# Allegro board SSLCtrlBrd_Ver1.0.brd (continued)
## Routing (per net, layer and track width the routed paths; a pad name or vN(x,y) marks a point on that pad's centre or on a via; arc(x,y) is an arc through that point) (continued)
+5V: length 235.9
  TOP w0.152: v2(19.81,61.75) 19.76,61.7 19.76,61.19 21.38,59.57 v2(21.61,59.57) ; U40.6 134.52,29.82 C109.2 v1(135.79,29.62) ; v2(18.08,97.86) 16.68,96.46 R30.2
  TOP w0.254: R18.1 v2(46.3,51.83) ; v2(118.85,34.98) 111.3,34.98 108.99,32.66 v2(108.99,29.79) ; v2(21.62,30.89) 20.83,31.67 C104.2 ; U39.6 v2(18.64,35.91) ; R25.1 v2(134.34,20.85) ; 11.48,75.34 12.18,76.03 v1(20.22,76.03) ; 11.48,75.34 18.49,75.34 20.18,73.65 v1(20.18,73.39) ; 11.48,75.34 J16.3 ; U5.5 103.2,23.09 103.69,23.57 106.38,23.57 v2(106.81,24) ; Q2.2 v2(134.24,19.23)
  TOP w0.305: v2(59.06,80.9) 58.35,80.19 58.35,75.95 57.29,74.89 57.29,69.84 ; R25.1 135.26,19.27 Q2.2
  GND w0.152: v2(21.41,64.31) 21.41,67.18 21.29,67.31 19.92,67.31 19.81,67.41 ; v2(18.08,97.86) 17.21,97.86 16.72,97.36 16.72,96.39
  GND w0.254: v2(19.81,61.75) 19.81,73.03 v1(20.18,73.39)
  GND w0.305: v2(121.87,85.47) 121.84,85.47 121.19,84.81 118.59,84.81 v2(118.26,85.14)
  POWER w0.254: v2(129.42,49.2) 130.2,49.2 132.41,51.41 ; v2(129.4,51.7) 130.6,51.7 131.55,52.65
  POWER w0.305: v2(129.53,46.75) 130.65,46.75 133.94,50.04 ; LS1.1 89.97,68.74 81.71,60.48 65.59,60.48 v2(64.31,61.75)
  BOTTOM w0.152: D34.2 v1(83.83,84.81) ; v2(56.14,97.87) RP7.3 RP7.2 RP7.1 ; D31.2 v1(20.18,73.39) ; v2(21.41,64.31) 21.28,64.45 D27.2 ; D33.2 v1(86.28,84.83) ; D13.2 v2(18.08,97.86) ; D12.2 v2(18.05,100.5) ; D35.2 v1(81.14,84.81) ; D30.2 v1(20.22,76.03) ; D29.2 v2(21.61,59.57)
  BOTTOM w0.254: D28.2 20.08,62.01 v2(19.81,61.75) ; J20.1 137.97,47.12 C76.2 141.48,46.48 142.22,47.22 142.22,48.15 RP11.3 RP11.2 RP11.1 ; C79.2 138.97,77.01 J14.3 ; v2(53.7,72.26) 55.58,74.14 TP2.1 ; J13.3 121.44,94.41 C70.2 ; v2(118.26,85.14) 119.41,86.28 D19.2 ; D23.2 v2(129.42,49.2) ; v2(139.19,90.68) 139.41,90.89 R36.2 ; D15.2 115.7,85.06 v2(115.34,84.71) ; J15.1 10.82,68.22 C83.2 v2(11.99,68.94) ; v2(59.64,62.27) 59.64,57.09 57.58,55.03 48.13,55.03 46.3,53.2 v2(46.3,51.83) ; J11.3 26.23,92.67 C61.2 ; D5.2 133.7,97.62 v2(134.06,97.26) ; D25.2 132.59,78.16 v2(133,78.56) ; v2(136.63,92) 136.63,92.46 136.72,92.55 R35.2 ; J16.3 11.15,75.01 C88.2 ; v2(112.96,84.73) 113.22,85 D16.2 ; D9.2 v2(56.46,83.29) ; v2(53.85,84.9) 53.99,84.76 D10.2 ; J12.1 114.48,93.42 C65.2 116.36,93.93 116.36,96.9 115.85,97.41 RP9.3 RP9.2 RP9.1 ; D18.2 v2(121.87,85.47) ; D24.2 v2(133.01,75.71) ; J17.1 84.03,93.09 C95.2 ; D14.2 110.74,85.21 v2(110.21,84.68) ; v2(106.81,24) 106.81,27.61 v2(108.99,29.79) ; C56.2 54.11,93.22 J10.1 ; D20.2 v2(129.4,51.7) ; D11.2 v2(51.52,84.72)
  BOTTOM w0.305: RP13.1 v2(5.53,68.16) ; RP13.1 v2(6.58,69.14) ; RP13.1 RP13.2 ; RP13.2 RP13.3 v2(8.21,69.11) ; RP13.2 v2(7.39,69.16) ; RP15.1 RP15.2 ; RP15.2 RP15.3 ; RP15.2 v2(86.34,98.43) ; D21.2 v2(129.53,46.75)
  vias: v2(17.17,20.8) v2(17.17,20.09) v2(17.22,19.41) v2(17.2,18.72) v2(17.88,20.83) v2(17.88,20.12) v2(17.88,19.41) v2(17.91,18.72) v2(18.59,20.8) v2(18.59,20.12) v2(63.63,63.75) v2(63.63,63.09) v2(63.63,62.43) v2(63.63,61.77) v2(63.63,61.11) v2(64.21,63.73) v2(64.26,63.07) v2(64.29,62.41) v2(64.31,61.11) v2(64.87,63.73) v2(64.9,63.07) v2(65.51,63.7) v2(65.53,63.07)
+VDD_A: length 13.1
  TOP w0.152: U1.22 v1(73.76,42.23)
  BOTTOM w0.254: C14.1 C13.1 73.71,41.81 73.71,42.19 v1(73.76,42.23) 73.71,42.28 FB1.2 73.71,43.89 73.18,44.42 69.65,44.42 69.12,44.96 69.12,46.33 69.97,47.19 R10.2
GND: length 337.3
  TOP w0.152: v2(39.37,55.25) R87.1 38.48,55.4 C84.1 ; v2(110.57,39.75) 110.03,39.22 U16.2 ; U3.1 77,52.97 v2(76.53,52.5) 76.35,52.32 76.35,49.89 77.4,48.84 78.95,48.84 79.23,49.13 U3.9 ; 102.77,41.45 v2(102.77,39.47) 102.87,39.37 ; 102.77,41.45 102.95,41.63 C71.1 ; 102.77,41.45 102.77,43.64 v2(102.97,43.84) U28.2 ; R104.1 v1(68.86,71.27) ; U31.2 102.95,39.29 102.87,39.37 ; R59.1 v1(96.26,72.95) ; v2(78.18,63.65) 78.82,64.29 R100.1 ; C96.1 v2(83.16,73.22) ; R65.1 v1(96.26,71.47) ; C99.1 18.06,11.51 v2(15.88,13.69) ; U17.2 v2(110.54,44.27) ; v2(84.25,54.28) 84.03,54.05 82.5,54.05 81.42,52.97 U3.18 ; C80.1 103.35,37.31 102.87,37.8 102.87,39.37 ; C80.1 103.35,34.98 R6.1 v2(104.55,34.85) ; C80.1 103.89,36.88 v2(104.35,36.42) ; C91.1 80.21,64.7 R100.1 ; R100.1 76.45,64.7 v2(76.37,64.62) C38.2 ; v2(25.66,32.39) C101.2 R116.2 v2(24.64,30.35) ; U18.3 99.02,54.03 v1(99.02,54.03) ; v2(130.23,31.09) U40.7 134.52,31.09 C109.1 v1(135.79,31.29) ; U19.3 v1(102.85,56.34) ; v2(84.33,59.36) Q1.2 83.26,58.19 R9.1 ; v2(97.91,38.6) 97.41,38.1 D3.2 ; C106.2 v2(122.46,33.96) ; R98.1 v1(68.86,72.75) ; C51.2 v2(129.29,90.47)
  TOP w0.203: C22.2 v1(88.52,27.1) C31.2 ; U1.99 85.07,41.28 84.43,40.64 v1(83.85,40.64) ; v1(69.19,41.53) 69.44,41.28 U1.27 ; v1(80.16,40.31) 80.16,42.14 79.76,42.55 U1.10 ; v1(135.49,84.86) 135.61,84.99 C53.2 ; U1.74 83.76,27.17 84.03,26.9 v1(84.89,26.9)
  TOP w0.254: C89.1 45.98,41.86 v2(45.98,40.34) U34.2 ; v2(117.53,69.67) 116.93,69.08 R78.1 R72.1 ; C43.2 v2(126.71,17.13) ; 56.93,32.13 56.46,31.67 U2.3 53.48,31.67 v2(53.19,31.95) ; 56.93,32.13 56.93,33.43 ; 56.93,32.13 56.93,31.3 56.03,30.4 U2.4 ; R45.1 62.38,49.2 ; 62.38,49.2 63.1,49.2 R13.2 63.12,50.47 62.77,50.83 ; 62.38,49.2 v2(62.38,48.39) ; v2(40.47,62.94) C57.1 40.3,63.96 R48.1 ; C45.2 v2(98.68,62.41) ; v2(97.06,22.38) C32.2 97.23,23.34 98.38,23.34 98.83,22.89 C33.2 ; C87.1 v2(30.37,59.58) ; R74.1 v2(111.05,64.64) ; v2(105.41,63.93) 106.35,64.87 R61.1 106.56,65.05 C66.1 ; 56.89,34.55 56.54,34.2 54.94,34.2 U2.1 ; 56.89,34.55 56.93,34.51 56.93,33.43 ; 56.89,34.55 C3.2 ; C69.1 v2(108.82,73.35) ; R19.2 47.65,49.09 v2(48.16,49.09) ; C78.1 118.98,54.05 v2(119.33,53.7) ; U2.1 v2(54.93,35.1) ; U2.1 54.75,34.39 C16.2 C12.2 50.45,34.42 U4.15 ; 56.93,33.43 57.42,32.94 U2.7 v2(62.47,32.94) ; 56.93,33.43 56.44,32.94 U2.2 v2(53.26,32.94) ; C23.2 65.51,28.35 C26.2 65.48,26.64 C25.2 v2(63.48,26.49) ; v2(95.46,55.07) C46.2 95.44,54.5 D4.1 93.37,54.28 v2(94.03,53.62) ; U38.16 40.78,24.82 v2(41.18,25.22) ; U39.7 v2(19.16,34.64) ; v2(33.73,52.83) 34.46,53.56 U32.7 ; v2(31.46,44.67) R91.1 31.42,45.64 R85.1 ; R53.1 R46.1 29.75,72.57 v2(30.63,73.46) ; C47.2 v2(101.93,60.93) ; C86.1 33.63,59.16 v2(33.07,59.72) ; v2(116,60.83) 115.22,60.05 U29.7 ; J3.8 v2(113.01,25.07) ; v2(74.9,44.68) 74.76,44.54 U1.20 ; C5.2 v2(89.51,43.33) ; U5.2 v2(101.22,21.79) ; J5.1 90.22,50.19 v2(89.49,50.93) ; C104.1 v2(17.3,31.67) ; U25.2 v2(45.77,44.73) ; D7.1 v2(139.05,84.97) ; U20.2 58.75,44.12 R41.1 C49.2 v2(59.64,47.68) ; C62.1 v2(44.3,46.94) ; C20.2 v2(125.96,21.18) ; U21.3 v2(130.28,95.5) ; C19.2 v2(38.69,30.99) ; R31.1 v2(104.57,54.33) ; C60.1 v2(42.95,72.48) ; C48.2 51.54,45.29 v2(50.78,46.05) ; U38.32 v2(24.06,8.32) ; C15.2 v2(46.05,35.66) ; 92.46,21.84 v2(93.12,21.84) ; C6.2 85.04,53.49 v2(84.25,54.28) 83.39,55.14 C8.2
  TOP w0.305: v2(104.03,70) 104.52,69.52 U26.7 ; v2(36.58,69.27) 36.64,69.27 37.27,68.64 U23.7 ; C73.1 v2(115.5,53.01) ; C72.1 v2(112.02,53.77) ; C20.2 127.61,22.93 C21.2 ; U14.3 129.61,15.86 128.93,15.18 C43.2 ; v2(76.46,69.95) 76.48,69.95 77.12,69.32 U35.7
  TOP w0.5: D8.1 v2(58.82,101.54) ; D8.1 v2(61.28,99.83) ; D8.1 v2(58.82,98.31) ; D6.2 v2(133.63,100.3) ; D32.1 v2(88.41,102.02) ; D32.1 v2(90.92,100.06) ; D32.1 v2(88.41,98.64)
  BOTTOM w0.152: v2(63.25,56.54) 62.66,55.96 TP4.1 ; D21.1 128.08,45.45 v2(127.74,45.11) ; D13.1 v2(18.25,96.56) ; D10.1 55.29,84.44 v2(55.42,84.58) ; D11.1 52.82,84.47 v2(52.88,84.53) ; U13.10 v2(77.42,17.02) ; v2(6.35,74.22) 7.14,75.01 C88.1 ; D35.1 v1(82.44,84.81) ; v2(11.97,91.59) 12.64,92.26 Q3.2 ; 56.97,96.47 56.72,96.47 55.98,95.73 55.98,95.48 ; D31.1 20.11,74.69 v2(20.42,75.01) ; v2(10.31,71.73) 10.82,71.22 C83.1 ; D30.1 20.03,77.33 v2(20.42,77.72) ; v2(13.16,90.47) 13.9,91.22 R33.1 ; C10.2 74.83,47.19 C2.1 ; C10.2 C9.2 ; C10.2 v2(73.28,46.56) ; v2(75.16,20.27) U13.15 U13.14 ; v2(84.46,95.3) 84.99,94.77 C95.1 ; C61.1 29.24,92.08 29.9,92.74 29.9,93.99 J11.1 ; D23.1 v2(128.09,47.9) ; 64.94,6.4 v1(68.05,6.4) 68.05,6.4 RP4.5 RP4.6 RP4.7 RP4.8 ; v1(82.93,47.7) 82.93,47.7 C1.1 ; D28.1 v2(21.16,63.31) ; v2(127,50.93) 127.53,50.4 D20.1 ; C79.1 142.75,77.01 v2(143.72,77.98) ; D34.1 v1(85.13,84.81) ; v2(68.28,33.4) 68.66,33.78 C52.2 ; U11.8 v2(65.8,16.44) ; 51.63,6.4 v1(54.76,6.4) 54.76,6.4 RP2.5 RP2.6 RP2.7 RP2.8 ; D29.1 21.28,60.87 v2(21.62,61.21) ; D33.1 v1(87.58,84.81) ; v2(84.15,17.91) C44.2 84.1,18.97 U13.4 ; 78.04,6.3 v1(81.31,6.3) 81.31,6.3 RP6.5 RP6.6 RP6.7 RP6.8 ; U13.3 U13.4 ; U13.4 U13.5 U13.6 80.76,17.67 80.62,17.53 80.62,16.71 80.88,16.46 81.99,16.46 U13.8 v2(83.56,16.37) ; D27.1 v2(20.74,66.38) ; U11.15 58.19,20.35 C42.2 56.16,18.31 v2(55.81,18.31) ; D12.1 v2(18.15,99.2) ; D9.1 v2(57.76,84.58)
  BOTTOM w0.203: v1(69.19,41.53) 69.22,41.56 C30.2 ; C27.2 83.85,39.9 v1(83.85,40.64)
  BOTTOM w0.254: C29.2 75.46,40.13 v2(75.03,40.56) ; C29.2 C13.2 ; C29.2 77.08,39.89 C18.2 ; C65.1 115.17,94.97 v2(115.67,95.48) ; D19.1 120.71,86.31 v2(120.86,86.16) ; C13.2 v2(73.96,40.54) ; C13.2 C14.2 v2(72.46,40.59) ; v2(123.65,86.44) 123.17,86.92 D18.1 ; v2(122.48,99.49) 121.44,98.45 C70.1 ; v2(32.14,22.04) R122.1 34.02,20.96 Q19.2 ; D16.1 v2(114.52,84.44) ; D5.1 132.89,96.73 v2(132.54,97.08) ; C76.1 136.45,46.48 v2(135.82,45.85) ; v2(141.4,92.86) 140.93,93.33 C50.2 ; D25.1 v2(133,76.86) ; v2(76.53,52.5) C4.2 79.25,52.5 C7.2 80.65,52.48 R3.1 ; D15.1 v2(117,84.46) ; D24.1 v2(132.99,74.41) ; C27.2 83.49,39.88 v1(82.93,39.32) C24.2 81.64,39.67 C28.2 v1(80.16,40.31) ; D14.1 v2(112.04,84.36)
  BOTTOM w0.5: v2(88.41,102.02) 88.41,100.1 ; 88.41,100.1 90.88,100.1 v2(90.92,100.06) ; 88.41,100.1 v2(88.41,98.64) ; v2(58.82,98.31) 55.98,95.48 C56.1
  vias: v2(13.85,15.09) v2(13.87,14.4) v2(13.82,13.67) v2(14.53,15.09) v2(14.53,14.4) v2(14.53,13.69) v2(15.17,15.04) v2(15.17,14.35) v2(15.17,13.64) v2(15.88,14.38) v2(15.93,15.06) v2(22.96,66.27) v2(22.99,65.58) v2(23.52,86.64) v2(23.55,85.93) v2(23.62,66.24) v2(23.65,65.56) v2(24.23,86.64) v2(24.26,85.9) v2(24.28,66.22) v2(24.28,65.56) v2(24.95,66.19) v2(24.92,65.56) v2(25.07,72.21) v2(25.05,71.53) v2(25.05,70.84) v2(25.05,70.18) v2(25.58,65.61) v2(25.61,66.27) v2(25.78,72.16) v2(25.76,71.5) v2(25.76,70.82) v2(25.71,70.16) v2(26.47,72.11) v2(26.42,71.45) v2(32.06,52.86) v2(32.06,52.04) v2(32.06,51.21) v2(32.88,52.06) v2(32.9,52.86) v2(32.9,51.21) v2(33.71,52.02) v2(33.71,51.16) v2(34.88,70.99) v2(34.88,70.21) v2(34.88,69.39) v2(35.74,70.97) v2(35.77,70.14) v2(35.77,69.32) v2(36.55,70.97) v2(36.58,70.1) v2(43.54,69.65) v2(43.61,68.83) v2(50.32,53.3) v2(50.32,52.29) v2(50.32,51.27) v2(51.33,53.3) v2(51.33,52.29) v2(51.33,51.27) v2(52.96,81.41) v2(52.96,80.7) v2(52.96,79.32) v2(53.01,80.01) v2(53.9,79.12) v2(53.95,78.46) v2(53.95,77.75) v2(54.59,79.12) v2(54.61,78.44) v2(54.61,77.75) v2(56.92,58.42) v2(56.92,57.71) v2(56.9,57.05) v2(57.58,57.02) v2(57.61,58.42) v2(57.61,57.71) v2(58.27,58.34) v2(58.22,57.66) v2(61.06,58.22) v2(61.09,57.15) v2(61.04,56.52) v2(61.11,59.13) v2(61.62,65.79) v2(62.16,59.13) v2(62.36,65.79) v2(63.05,59.16) v2(63.07,58.22) v2(63.17,57.3) v2(67.57,56.69) v2(67.67,58.67) v2(67.62,58.06) v2(67.59,57.43) v2(68.23,58.06) v2(68.23,57.4) v2(68.2,56.69) v2(68.33,58.67) v2(74.78,69.98) v2(74.81,71.65) v2(74.81,70.82) v2(75.62,71.65) v2(75.62,70.82) v2(75.62,69.98) v2(76.43,71.63) v2(76.46,70.79) v2(80.72,82.96) v2(80.75,82.27) v2(80.77,81.58) v2(80.77,80.92) v2(83.54,70.28) v2(83.52,69.55) v2(102.16,71.88) v2(102.16,71.04) v2(102.16,70.16) v2(103,71.86) v2(103.02,71.02) v2(103.08,70.13) v2(103.86,71.86) v2(103.84,70.94) v2(110.9,70.36) v2(110.9,69.72) v2(114.66,82.35) v2(114.63,81.64) v2(114.66,80.95) v2(114.66,80.26) v2(115.29,82.32) v2(115.29,81.66) v2(115.32,80.95) v2(115.98,81.64) v2(116,82.35) v2(116,80.95) v2(116,62.48) v2(116.03,61.67) v2(116.64,82.32) v2(116.64,81.66) v2(116.66,80.95) v2(116.77,61.67) v2(116.79,62.46) v2(116.82,60.81) v2(117.53,62.46) v2(117.53,61.65) v2(123.67,45.87) v2(123.65,45.19) v2(124.28,45.19) v2(124.26,44.48) v2(124.23,43.79) v2(124.31,45.85) v2(124.87,43.79) v2(124.94,45.85) v2(124.89,45.21) v2(124.89,44.53) v2(125.58,45.19) v2(125.53,44.42) v2(125.53,43.79) v2(125.61,45.87)
GND_OPT: length 91.8
  TOP w0.152: U17.3 114.15,44.27 113.82,43.94 113.82,39.83 114.45,39.19 115.85,39.19 U16.3 116.56,39.22 v1(117.27,39.93) 117.27,41.73 118.39,42.85 v1(118.39,51.08)
  TOP w0.203: v1(119.53,37.62) 122.33,34.82 134.57,34.82 137.34,37.59 139.01,37.59 U22.2
  BOTTOM w0.152: v1(118.39,51.08) 118.39,56.13 117.83,56.69 117.83,59.97 117.83,60.03 119.92,62.11 119.92,75.23 121.72,77.04 126.34,77.04 128.42,79.12 128.42,82.85 129.36,83.79 132.1,83.79 J9.4 ; v1(119.53,37.62) 117.27,39.88 v1(117.27,39.93)
VBAT: length 58.4
  TOP w0.152: C37.1 56.23,50.87
  TOP w0.508: U19.6 105.77,56.34 104.93,57.18 C47.1 104.93,61.49 102.39,64.03 98.88,64.03 91.95,70.97 91.95,76.2 v2(91.26,76.89) ; R43.1 56.8,51.27 C37.1
  GND w1.016: v2(55.42,52.81) 55.42,69.52 61.04,75.13 v2(61.04,76.23)
  vias: v2(14.38,72.54) v2(14.35,71.88) v2(14.94,71.88) v2(15.01,72.54) v2(15.57,71.83) v2(15.62,72.52) v2(20.88,84) v2(20.86,83.31) v2(20.86,82.6) v2(20.86,81.74) v2(20.86,81) v2(20.91,80.42) v2(21.54,84.02) v2(21.54,83.34) v2(21.49,82.6) v2(21.54,81.79) v2(21.59,81.13) v2(21.59,80.44) v2(22.28,81.15) v2(22.3,80.44) v2(22.99,81.15) v2(22.99,80.44) v2(55.32,53.44) v2(55.42,52.2) v2(55.88,52.83) v2(56.36,52.81) v2(56.87,52.81) v2(57.38,52.76) v2(60,76.15) v2(60.51,76.17) v2(61.09,78.64) v2(61.09,77.34) v2(61.04,76.81) v2(61.11,77.95) v2(61.57,77.34) v2(61.6,76.78) v2(61.6,76.2) v2(90.07,78.36) v2(90.07,77.77) v2(90.1,77.17) v2(90.71,78.36) v2(90.71,77.77) v2(90.71,77.17) v2(91.26,77.44) v2(91.29,78.05) v2(124.28,92.08) v2(124.26,91.41) v2(124.28,90.81) v2(124.28,90.14) v2(124.94,92.05) v2(124.94,91.39) v2(124.92,90.78) v2(124.92,90.14) v2(136.12,40.94) v2(136.76,40.92) v2(137.42,40.92) v2(138.03,40.94) v2(138.2,41.63) v2(138.86,41.61) v2(139.55,41.55)
A_OUT_1: length 11.9
  TOP w0.152: 32.82,86.84 32.88,86.91
  TOP w0.254: v2(33.81,80.19) 33.81,77.34 32.54,76.07 32.54,72.08 32.98,71.64 U23.22
  BOTTOM w1.016: J10.8 36.44,95.57 TP19.1
  vias: v2(31.47,86.92) v2(31.47,86.18) v2(31.45,85.47) v2(32.18,86.92) v2(32.18,86.18) v2(32.16,85.5) v2(32.87,86.92) v2(32.87,86.21) v2(32.87,85.5) v2(33.84,80.8) v2(34.5,80.82) v2(34.5,80.16)
A_OUT_2: length 15.7
  TOP w0.254: v2(93.65,80.09) 93.19,79.63 93.19,75.95 93.98,75.16 97.94,75.16 98.99,74.12 99.44,74.12 99.94,73.62 99.94,72.73 100.15,72.52 U26.22
  BOTTOM w1.016: 95.7,93.42 95.7,95.41 TP27.1
  vias: v2(90.32,86.82) v2(90.91,86.84) v2(90.96,86.26) v2(90.96,85.57) v2(91.57,86.82) v2(91.54,86.18) v2(91.54,85.6) v2(92.18,86.18) v2(92.15,85.55) v2(92.2,86.79) v2(93.02,80.75) v2(93.02,80.09) v2(93.65,80.75)
A_OUT_3: length 12.7
  TOP w0.254: v2(124.64,68.99) 124.31,69.32 120.73,69.32 119.51,68.1 119.51,66.17 118.25,64.91 U29.22
  BOTTOM w1.016: J20.8 TP35.1
  vias: v2(124.67,69.62) v2(125.35,69.6) v2(125.33,68.99) v2(129.8,72.06) v2(129.82,71.35) v2(129.85,70.64) v2(130.51,72.06) v2(130.53,71.35) v2(130.56,70.66) v2(131.22,72.06) v2(131.22,71.35) v2(131.24,70.66)
A_OUT_4: length 13.2
  TOP w0.254: v2(24.34,44.32) 27.74,44.32 28.63,45.21 28.63,48.13 29.34,48.84 30.58,48.84 U32.22
  BOTTOM w1.016: J15.8 9.97,49.44 TP43.1
  vias: v2(17.63,43.46) v2(17.6,42.77) v2(17.6,42.09) v2(18.34,43.46) v2(18.32,42.75) v2(18.32,42.04) v2(19.05,43.43) v2(19.03,42.75) v2(19,42.06) v2(23.68,44.98) v2(23.7,44.35) v2(24.34,44.98)
A_OUT_5: length 18.5
  TOP w0.254: v2(63.22,80.16) 63.43,79.96 63.43,76.35 64.16,75.62 66.58,75.62 68.18,74.02 71.96,74.02 72.57,73.41 72.57,72.61 72.86,72.32 U35.22
  BOTTOM w1.016: J17.8 66.09,96.16 TP51.1
  vias: v2(60.89,86.26) v2(60.89,85.57) v2(60.91,86.94) v2(61.57,86.26) v2(61.6,86.94) v2(61.6,85.57) v2(62.28,86.94) v2(62.28,86.26) v2(62.28,85.57) v2(63.25,80.8) v2(63.88,80.77) v2(63.88,80.14)
ADC_BAT_V: length 23.9
  TOP w0.152: v1(72.06,35.71) 72.06,36.12 71.4,36.78 U1.36
  TOP w0.254: R43.2 R45.2 60.17,49.2 60.71,48.67 60.71,46.94 62.36,45.29 62.36,43.99 69.57,36.78 U1.36
  BOTTOM w0.152: C52.1 69.75,35.71 v1(72.06,35.71)
ADC_CAP_V: length 130.1
  TOP w0.152: v1(137.92,85.78) 137.34,85.78 C53.1 ; v1(72.95,35.84) 72.9,35.89 72.9,36.53 72.14,37.28 U1.35 69.86,37.28 66.32,40.82 66.32,42.85 64.97,44.2 v1(64.6,44.2) ; v1(99.95,46.23) 99.9,46.28 97.44,46.28 v1(97.03,45.87) ; R37.1 60.28,42.52 v1(60.63,42.52)
  TOP w0.203: D7.3 139.59,87.45 R44.2 C53.1
  BOTTOM w0.152: v1(137.92,85.78) 135.51,85.78 134.83,86.46 127.43,86.46 126.82,85.85 126.82,79.6 125.58,78.36 120.17,78.36 118.26,76.45 118.26,66.68 115.85,64.26 113.49,64.26 110.77,61.54 110.77,51.26 107.62,48.11 101.58,48.11 99.95,46.48 v1(99.95,46.23) ; v1(97.03,45.87) 96.85,45.69 96.85,44.32 92.08,39.55 89.87,39.55 88.14,37.82 88.14,35.2 86.95,34.01 81.38,34.01 81,33.63 76.36,33.63 74.15,35.84 v1(72.95,35.84) ; v1(60.63,42.52) 62.54,42.52 64.22,44.2 v1(64.6,44.2)
B_OUT_1: length 14.4
  TOP w0.254: v1(34.39,74.52) 34.77,74.15 U23.20
  BOTTOM w0.254: v1(34.39,74.52) 34.75,74.52 36.04,75.82 38.91,75.82 40.06,76.96 v2(40.06,80.29)
  BOTTOM w1.016: TP18.1 38.94,95.53 J10.7
  vias: v2(37.65,87.05) v2(37.65,86.33) v2(37.62,85.62) v2(38.33,87.02) v2(38.33,86.31) v2(38.33,85.62) v2(39.04,87.02) v2(39.04,86.33) v2(39.04,85.62) v2(40.06,80.95) v2(40.69,80.92) v2(40.72,80.34)
B_OUT_2: length 10.7
  TOP w0.152: 99.54,81.97 Q8.3
  TOP w0.254: v2(99.19,80.09) 99.27,80.01 99.27,76.05 100.03,75.29 101.48,75.29 102.02,74.74 U26.20
  BOTTOM w1.016: TP26.1 98.2,95.29 98.2,93.42
  vias: v2(96.73,86.64) v2(96.73,85.95) v2(96.7,85.24) v2(97.46,86.61) v2(97.44,85.93) v2(97.44,85.22) v2(98.17,86.66) v2(98.17,85.95) v2(98.17,85.24) v2(99.24,80.95) v2(99.88,80.95) v2(99.85,80.11)
B_OUT_3: length 8.1
  TOP w0.254: v2(124.59,63.42) 124.46,63.3 120.47,63.3 119.73,62.55 U29.20
  BOTTOM w1.016: J20.7 140.26,64.44 TP34.1
  vias: v2(124.61,62.76) v2(125.28,63.42) v2(125.3,62.74) v2(129.9,65.89) v2(129.92,65.2) v2(129.9,64.47) v2(130.61,65.89) v2(130.61,65.18) v2(130.61,64.47) v2(131.32,65.89) v2(131.32,65.18) v2(131.32,64.47)
B_OUT_4: length 8.4
  TOP w0.254: v2(24.34,51.18) 24.46,51.06 U32.20
  BOTTOM w1.016: TP42.1 9.91,51.94 J15.7
  vias: v2(17.63,49.63) v2(17.63,48.95) v2(17.63,48.23) v2(18.32,49.63) v2(18.32,48.92) v2(18.32,48.23) v2(19,49.63) v2(19,48.9) v2(19,48.18) v2(23.65,51.18) v2(23.62,50.55) v2(24.31,50.55)
B_OUT_5: length 13.5
  TOP w0.254: v2(70.08,80.19) 69.85,79.96 69.85,75.87 70.56,75.16 73.56,75.16 v2(74.02,74.7) 74.04,74.7 74.62,74.13 U35.20
  BOTTOM w1.016: J17.7 68.59,96.15 TP50.1
  vias: v2(67.08,86.87) v2(67.06,86.18) v2(67.03,85.52) v2(67.77,86.87) v2(67.74,86.21) v2(67.72,85.52) v2(68.46,86.89) v2(68.46,86.21) v2(68.46,85.52) v2(69.42,80.87) v2(69.39,80.21) v2(70.06,80.85)
BLE_RX: length 41.7
  TOP w0.152: U1.56 74.76,24.26 72.11,21.62 55.07,21.62 54.43,20.98 46.81,20.98 44.06,18.22 U38.10
BLE_TX: length 40.5
  TOP w0.152: U1.55 74.26,24.57 71.73,22.05 54.38,22.05 53.85,21.51 46.53,21.51 44.34,19.32 U38.11
BOOT0: length 49.6
  TOP w0.152: v1(92.36,24.08) 92.33,24.05 v1(86.41,24.05) ; U1.94 91.37,38.78 92.13,38.02 92.13,33.63 94.82,30.94 v1(94.82,29.82) ; v1(77.6,15.34) v1(85.45,15.34)
  BOTTOM w0.152: v1(85.45,15.34) 85.45,23.09 v1(86.41,24.05) ; RP5.1 78.02,13.65 77.6,14.07 v1(77.6,15.34) ; v1(94.82,29.82) 94.82,26.39 92.51,24.08 v1(92.36,24.08)
BOOT1: length 17.6
  TOP w0.152: v1(64.75,42.57) 64.7,42.62 64.7,42.67 63.6,43.76 63.6,47.52 64.8,48.72 R13.1 ; v1(64.37,40.92) 64.37,40.89 68.98,36.28 U1.37
  BOTTOM w0.152: v1(64.37,40.92) 64.37,41 64.75,41.38 64.75,42.57 v1(64.75,42.57)
BUZZER: length 17.1
  TOP w0.152: U1.16 76.76,44.51 74.53,46.74 74.53,54.2 R8.1
C_OUT_1: length 17
  TOP w0.254: v1(36.58,74.96) 35.77,74.14 U23.18
  BOTTOM w0.254: v2(46.33,80.24) 45.54,80.24 40.26,74.96 v1(36.58,74.96)
  BOTTOM w1.016: J10.6 41.44,95.49 TP17.1
  vias: v2(44.02,86.94) v2(44.02,86.26) v2(44.02,85.55) v2(44.71,86.94) v2(44.73,86.26) v2(44.73,85.55) v2(45.42,86.94) v2(45.42,86.26) v2(45.42,85.55) v2(46.31,80.92) v2(46.99,80.95) v2(46.99,80.31)
C_OUT_2: length 9.7
  TOP w0.254: v2(105.44,80.11) 105.36,80.04 105.36,78.21 103.02,75.86 U26.18
  BOTTOM w1.016: TP25.1 100.7,95.39 100.7,93.42
  vias: v2(102.87,86.77) v2(102.87,86.06) v2(102.87,85.37) v2(103.56,86.77) v2(103.56,86.08) v2(103.58,85.37) v2(104.27,86.77) v2(104.27,86.06) v2(104.27,85.34) v2(105.41,80.75) v2(106.07,80.8) v2(106.1,80.09)
C_OUT_3: length 11.4
  TOP w0.254: U29.18 119.12,61.54 120.02,61.54 120.3,61.27 120.77,61.27 120.8,61.24 122.4,61.24 123.47,60.17 123.47,57.63 124.59,56.52 v2(124.61,56.52)
  BOTTOM w1.016: J20.6 140.26,61.94 TP33.1
  vias: v2(124.61,57.18) v2(125.25,57.18) v2(125.28,56.52) v2(130.18,59.51) v2(130.13,58.8) v2(130.13,58.14) v2(130.69,58.17) v2(130.76,59.49) v2(130.74,58.83) v2(131.37,58.78) v2(131.32,58.12) v2(131.4,59.49)
C_OUT_4: length 11.3
  TOP w0.254: U32.18 29.15,52.06 26.52,54.69 26.52,56.29 26.11,56.69 24.34,56.69 24.28,56.74
  BOTTOM w1.016: J15.6 9.97,54.44 TP41.1
  vias: v2(17.68,55.85) v2(17.66,55.17) v2(17.63,54.46) v2(18.42,55.85) v2(18.42,55.17) v2(18.39,54.48) v2(19.1,55.85) v2(19.1,55.14) v2(19.13,54.46) v2(23.68,57.4) v2(23.68,56.74) v2(24.34,57.4) v2(24.34,56.72)
C_OUT_5: length 9.9
  TOP w0.254: U35.18 75.62,79.53 v2(76.25,80.16)
  BOTTOM w1.016: J17.6 71.09,96.09 TP49.1
  vias: v2(73.23,86.89) v2(73.2,86.18) v2(73.2,85.47) v2(73.89,86.89) v2(73.89,86.18) v2(73.92,85.47) v2(74.58,86.87) v2(74.58,86.18) v2(74.6,85.47) v2(75.59,80.92) v2(75.62,80.19) v2(76.23,80.92)
CAP_V_IN: length 4.8
  TOP w0.254: R44.1 133.32,87.45 J9.2
  BOTTOM w0.254: J9.2 133.27,89.82 TP12.1
CHIP: length 60.1
  TOP w0.152: R31.2 102.87,52.93 102.87,54.69 102.49,55.07 U19.4 ; R31.2 102.9,51.94 105.51,49.33 105.51,46.99 v1(105.34,46.81) ; R31.2 102.57,52.58 v1(102.06,52.58) ; U1.26 69.96,41.78 69.04,42.7 69.04,43.94 67.85,45.14 v1(67.85,45.8) ; R27.2 107.39,45.14 v1(107.39,44.02)
  BOTTOM w0.152: v1(67.85,45.8) 67.85,47.6 68.94,48.69 91.09,48.69 94.97,52.58 v1(102.06,52.58) ; v1(107.39,44.02) 105.34,46.08 v1(105.34,46.81)
CHIP_OUT: length 61
  TOP w0.152: U19.5 107.14,55.07 v1(107.83,54.38) ; U17.4 114.33,46.81 114.1,47.04 114.1,49.1 110.39,52.81 v1(107.06,52.81)
  BOTTOM w0.152: TP11.1 128.55,87.55 126.39,87.55 113.87,75.03 113.87,70.1 107.55,63.78 107.55,54.66 v1(107.83,54.38) 107.83,53.57 v1(107.06,52.81)
  BOTTOM w0.254: TP11.1 130.71,87.53 J9.1
DIP_SW_CLK: length 26.4
  TOP w0.152: v1(78.46,22.33) 79.26,23.12 U1.65
  BOTTOM w0.152: U11.2 68.79,20.35 70.06,19.08 72.62,19.08 75.92,22.38 78.41,22.38 v1(78.46,22.33) 78.46,22.3 80.5,20.27 U13.2
DIP_SW_D: length 35
  TOP w0.152: v1(55.86,17.02) 56.54,17.7 74.75,17.7 79.76,22.71 U1.66
  BOTTOM w0.152: U11.9 58.85,16.46 56.29,16.46 55.86,16.89 v1(55.86,17.02)
DIP_SW_LD: length 25.7
  TOP w0.152: v1(78.28,23.24) 78.76,23.71 U1.64
  BOTTOM w0.152: U11.1 68.97,21 70.44,19.53 72.24,19.53 75.9,23.19 78.23,23.19 v1(78.28,23.24) 78.49,23.24 80.81,20.92 U13.1
ENCODER_A_1: length 29.5
  TOP w0.152: U1.23 73.26,44.91 70.79,47.37 64.52,47.37 64.49,47.4 v1(64.37,47.4) ; U25.6 48.95,45.67 v1(48.97,45.64)
  BOTTOM w0.152: v1(64.37,47.4) 64.34,47.42 62,45.09 49.53,45.09 v1(48.97,45.64)
ENCODER_A_2: length 49.2
  TOP w0.152: v1(94.49,43.79) 98.22,43.79 99.11,42.9 U28.6 ; U1.31 69.08,39.28 68.56,39.8 68.56,43.61 v1(67.24,44.93) ; v1(87.12,49.33) 87.43,49.33 88.62,48.13 88.62,46 89.33,45.29 v1(89.33,45.14)
  BOTTOM w0.152: v1(89.33,45.14) 90.43,44.04 94.24,44.04 v1(94.49,43.79) ; v1(67.24,44.93) 67.24,47.75 68.56,49.07 86.74,49.07 87,49.33 v1(87.12,49.33)
ENCODER_A_3: length 16
  TOP w0.152: U31.6 100.46,38.35 99.98,37.87 v1(99.98,37.85) ; U1.92 88.18,37.78 88.8,37.16 91.21,37.16 v1(91.24,37.16)
  BOTTOM w0.152: v1(91.24,37.16) 91.26,37.19 99.29,37.19 99.95,37.85 v1(99.98,37.85)
ENCODER_A_4: length 44.6
  TOP w0.152: v1(82.15,32.28) 84.15,30.28 U1.77 ; v2(66.43,33.11) 66.43,33.24 60.51,39.17 51.56,39.17 49.35,41.38 47.68,41.38 U34.6
  BOTTOM w0.152: v2(66.43,33.11) 66.52,33.01 66.52,32.63 67.38,31.78 69.7,31.78 71.35,33.43 73.03,33.43 73.03,33.43 75.01,33.43 75.95,32.49 81.97,32.49 82.15,32.31 v1(82.15,32.28)
ENCODER_B_1: length 29
  TOP w0.152: v1(48.74,43.71) 48.67,43.79 U25.4 ; U1.24 72.76,44.9 70.64,47.02 64.87,47.02 64.44,46.59 v1(64.42,46.59)
  BOTTOM w0.152: v1(64.42,46.59) 62.56,44.73 49.76,44.73 v1(48.74,43.71)
ENCODER_B_2: length 50.4
  TOP w0.152: U1.32 68.89,38.78 68.12,39.55 68.12,43.26 66.68,44.7 v1(66.68,45.62) ; v1(90.3,45.16) 90.3,45.24 89.05,46.48 89.05,48.54 87.63,49.96 86.44,49.96 v1(86.11,49.63) ; v1(94.9,44.7) 99.19,44.7 99.27,44.78 U28.4
  BOTTOM w0.152: v1(94.9,44.7) 94.71,44.89 90.57,44.89 v1(90.3,45.16) ; v1(86.11,49.63) 68.45,49.63 66.68,47.85 66.68,46.4 66.68,46.4 v1(66.68,45.62)
ENCODER_B_3: length 17.1
  TOP w0.152: v1(90.43,37.72) 89.23,37.72 88.67,38.28 U1.93 ; v1(99.77,39.8) 99.8,39.8 100.23,40.23 U31.4
  BOTTOM w0.152: v1(99.77,39.8) 99.77,38.71 98.78,37.72 v1(90.43,37.72)
ENCODER_B_4: length 46.5
  TOP w0.152: U1.89 84.87,36.28 83.52,34.93 83.52,32.54 v1(83.54,32.51) ; v1(65.51,32.89) 59.82,38.58 51.03,38.58 50.22,39.4 U34.4
  BOTTOM w0.152: v1(83.54,32.51) 82.76,31.72 81.69,31.72 81.31,32.11 75.85,32.11 75.82,32.13 75.8,32.13 74.86,33.07 71.56,33.07 71.49,32.99 71.48,32.99 69.91,31.42 66.42,31.42 65.51,32.33 v1(65.51,32.89)
FSYNC: length 9.1
  TOP w0.152: v1(80.29,51.61) 80.23,51.55 U3.11 80.26,49.77 U1.9
  BOTTOM w0.152: R3.2 80.29,51.36 v1(80.29,51.61)
HA_A_1: length 39.6
  TOP w0.152: v1(33.91,66.57) 34.27,66.93 34.27,67.72 U23.1
  BOTTOM w0.152: v1(33.91,66.57) 33.91,66.55 34.32,66.14 39.8,66.14 41.33,67.67 41.33,73.36 43.82,75.84 49.89,75.84 51.72,77.67 51.72,81.89 52.91,83.08 54.28,83.08 54.66,83.46 54.66,85.76 D10.3 54.41,86.01 RP8.2
HA_A_2: length 31.3
  TOP w0.152: U26.1 101.52,66.95 v1(101.47,66.9)
  BOTTOM w0.152: RP10.2 114.07,87.4 D16.3 113.87,84.58 111.18,81.89 111.18,72.82 106.43,68.07 103.35,68.07 103.08,67.8 103.08,67.18 102.79,66.9 v1(101.47,66.9)
HA_A_3: length 34.2
  TOP w0.152: U29.1 113.71,63.05 113.54,63.22 v1(113.39,63.22)
  BOTTOM w0.152: RP12.2 130.72,48.51 D23.3 128.06,48.55 127.87,48.74 116.36,48.74 113.29,51.82 113.29,61.44 112.93,61.8 112.93,62.76 v1(113.39,63.22)
HA_A_4: length 31.7
  TOP w0.152: v1(37.19,49.96) 36.59,50.56 U32.1
  BOTTOM w0.152: RP14.2 D28.3 21.36,62.66 23.07,60.96 33.53,60.96 36.3,58.19 36.3,52.68 37.18,51.8 37.18,49.97 v1(37.19,49.96)
HA_A_5: length 32.2
  TOP w0.152: U35.1 74.12,67.26 v1(73.99,67.14)
  BOTTOM w0.152: v1(73.99,67.14) 74.4,66.73 75.49,66.73 75.67,66.9 75.67,67.72 75.9,67.95 81.08,67.95 82.2,69.06 82.2,83.59 83.24,84.63 83.24,86.66 83.97,87.4 D34.3 84.43,87.45 RP16.2
HA_B_1: length 36.4
  TOP w0.152: U23.3 35.26,67.72 35.26,66.77 v1(35.32,66.7)
  BOTTOM w0.152: RP8.3 53.6,86.92 53.24,86.56 52.33,86.56 52.17,86.41 D11.3 52.17,83.19 51.36,82.37 51.36,77.93 49.68,76.25 43.66,76.25 40.97,73.56 40.97,67.84 39.83,66.7 v1(35.32,66.7)
HA_B_2: length 29.2
  TOP w0.152: v1(102.46,67.61) 102.52,67.67 U26.3
  BOTTOM w0.152: RP10.3 113.26,87.45 112.97,87.16 D14.3 111.39,84.8 110.8,84.2 110.8,73.03 106.2,68.43 103.2,68.43 102.46,67.68 v1(102.46,67.61)
HA_B_3: length 33.6
  TOP w0.152: U29.3 114.34,62.05 v1(113.49,62.05)
  BOTTOM w0.152: 130.68,50 130.53,49.85 128.51,49.85 127.79,49.12 116.51,49.12 113.69,51.94 113.69,61.85 v1(113.49,62.05) ; 130.68,50 130.68,49.89 131.24,49.33 133.31,49.33 ; 130.68,50 D20.3
HA_B_4: length 29
  TOP w0.152: v1(36.41,51.5) 36.35,51.56 U32.3
  BOTTOM w0.152: v1(36.41,51.5) 35.94,51.97 35.94,57.94 33.4,60.48 23.01,60.48 22.76,60.22 D29.3 18.89,61.35 18.39,61.85 RP14.3
HA_B_5: length 30.1
  TOP w0.152: U35.3 75.12,67.55 75.11,67.54 v1(75.11,67.34)
  BOTTOM w0.152: RP16.3 83.62,87.86 83.12,87.36 D35.3 81.79,69.16 80.98,68.35 75.54,68.35 75.12,67.93 75.12,67.54 75.11,67.53 v1(75.11,67.34)
HA_C_1: length 41.9
  TOP w0.152: v1(36.53,65.51) 36.53,65.91 36.27,66.17 36.27,67.72 U23.5
  BOTTOM w0.152: v1(36.53,65.51) 36.58,65.56 39.8,65.56 41.71,67.46 41.71,73.2 43.89,75.39 49.99,75.39 52.07,77.47 52.07,81.51 53.11,82.55 56.64,82.55 57.08,82.98 57.08,85.74 D9.3 56.55,86.33 55.81,86.33 55.22,86.92 RP8.1
HA_C_2: length 31.7
  TOP w0.152: v1(103.68,67.48) 103.68,67.48 103.52,67.64 U26.5
  BOTTOM w0.152: v1(103.68,67.48) 106.42,67.48 111.53,72.59 111.53,81.57 113.7,83.74 115.67,83.74 116.33,84.4 116.33,87.18 D15.3 115.17,87.2 114.89,87.48 RP10.1
HA_C_3: length 35.8
  TOP w0.152: v1(112.68,61.24) 112.86,61.05 U29.5
  BOTTOM w0.152: v1(112.68,61.24) 112.88,61.04 112.88,51.56 116.21,48.23 127.26,48.23 127.41,48.08 127.41,46.46 127.76,46.1 D21.3 131.07,46.1 132.67,47.7 RP12.1
HA_C_4: length 33.4
  TOP w0.152: U32.5 37.23,52.56 37.29,52.5 v1(37.44,52.5)
  BOTTOM w0.152: v1(37.44,52.5) 36.71,53.24 36.71,58.5 33.73,61.47 23.19,61.47 22.13,62.53 22.13,64.74 21.77,65.1 D27.3 18.89,63.97 18.39,63.47 RP14.1
HA_C_5: length 33.1
  TOP w0.152: v1(76.25,67.34) 76.25,67.41 76.12,67.55 U35.5
  BOTTOM w0.152: RP16.1 85.24,87.86 85.65,87.45 86.88,87.45 D33.3 86.93,84.47 86.46,84 83.44,84 82.55,83.11 82.55,68.83 81.28,67.56 76.47,67.56 v1(76.25,67.34)
I2C_SCL: length 73.6
  TOP w0.152: v1(78.89,54.51) 78.74,54.36 78.74,53.65 U3.23 ; U2.6 58.11,31.67 56.82,30.38 R1.1 ; 61.78,31.67 62.17,31.28 U1.47 71.59,31.28 73.1,29.77 77.09,29.77 77.42,30.1 v1(77.47,30.1) ; v1(92.69,34.8) 92.69,49.2 87,54.89 v1(86.44,54.89)
  TOP w0.203: 61.78,31.67 U2.6
  BOTTOM w0.152: v1(77.47,30.1) 77.7,30.33 79.08,30.33 79.71,29.69 82.63,29.69 84.48,31.55 89.91,31.55 92.69,34.32 92.69,34.79 v1(92.69,34.8) ; v1(78.89,54.51) 79.28,54.89 v1(86.44,54.89)
I2C_SDA: length 74.8
  TOP w0.152: v1(93.42,34.26) 93.41,34.28 93.41,49.49 87.02,55.88 v1(86.72,55.88) ; v1(78.23,55.07) 78.23,53.64 U3.24 ; R2.1 58.19,29.92 58.67,30.4 U2.5 61.72,30.4 62.1,30.78 U1.48 71.41,30.78 72.52,29.67 72.7,29.67 73.02,29.35 77.74,29.35 78.16,29.77 v1(78.19,29.77)
  BOTTOM w0.152: v1(78.19,29.77) 79.13,29.77 79.57,29.34 82.78,29.34 83.21,29.77 83.24,29.77 84.58,31.12 90.27,31.12 v1(93.42,34.26) ; v1(78.23,55.07) 79.05,55.88 v1(86.72,55.88)
IR_BALL_DECT: length 105.5
  TOP w0.152: U21.4 129.52,91.87 125.58,87.94 125.58,86 v1(125.63,85.95) ; v1(94.17,49.87) 87.48,56.57 78.11,56.57 75.24,53.7 75.24,46.76 77.26,44.74 U1.15
  TOP w0.203: R42.2 130.85,97 129.95,97 129.34,96.39 129.34,93.55 130.28,92.61 U21.4
  BOTTOM w0.152: v1(94.17,49.87) 94.17,50.05 94.77,50.65 107.19,50.65 109.02,52.48 109.02,64.64 114.33,69.95 114.33,74.68 125.61,85.95 v1(125.63,85.95)
IR_BALL_DECT_IN: length 8.7
  TOP w0.203: v1(131.17,93.75) 131.22,93.8 U21.2
  BOTTOM w0.203: v1(131.17,93.75) 132.43,93.75 D5.3
  BOTTOM w0.254: D5.3 R40.1
  BOTTOM w0.305: R40.1 135.27,94.93 R35.1
IR_PWM: length 116.4
  TOP w0.152: v1(24.13,90.17) v1(27.53,90.17) ; U1.95 84.87,39.28 84.18,38.59 84.18,37.01 82.38,35.21 v1(82.37,35.21)
  BOTTOM w0.152: v1(27.53,90.17) 27.76,90.17 29.95,87.99 29.95,68.96 31.37,67.54 31.37,65.91 32.92,64.36 34.22,64.36 41.96,56.62 41.96,43.38 46.28,39.07 61.32,39.07 63.27,37.11 74.2,37.11 75.9,35.41 80.8,35.41 81.12,35.72 81.85,35.72 v1(82.37,35.21) ; R32.1 v1(24.13,90.17)
JTAG_SWDCLK: length 27.1
  TOP w0.152: U1.76 87.75,29.78 92.54,24.99 v1(100.76,24.99) ; R6.2 101.51,34.81 J1.3
  BOTTOM w0.152: J1.3 101.4,30.39 101.4,25.63 v1(100.76,24.99)
JTAG_SWDIO: length 30.3
  TOP w0.152: R5.2 91.16,25.3 91.82,24.64 100.15,24.64 100.48,24.31 103.84,24.31 v1(103.89,24.36)
  TOP w0.203: R5.2 83.42,25.88 82.76,26.54 U1.72
  BOTTOM w0.152: v1(103.89,24.36) 103.89,30.13 J1.2
LED_CLK: length 71.9
  TOP w0.152: v1(75.41,37.36) 75.41,37.39 75.14,37.67 74.27,37.67 72.16,39.78 U1.30 ; v1(120.93,29.59) 118.04,29.59 114.2,33.43 v1(114.05,33.43) ; v1(89.49,35.79) 89.17,35.79 88.35,36.6 87.38,36.6 v1(87.35,36.63) ; R24.2 131.21,24.23 129.36,26.09 123.34,26.09 v1(123.29,26.04)
  BOTTOM w0.152: v1(120.93,29.59) 123.29,27.23 v1(123.29,26.04) ; v1(87.35,36.63) 86.39,35.66 83.97,35.66 82.91,36.73 77.83,36.73 77.19,37.36 v1(75.41,37.36) ; v1(89.49,35.79) 89.82,35.46 94.77,35.46 96.24,33.99 113.49,33.99 v1(114.05,33.43)
LED_COMM: length 25.9
  TOP w0.152: U1.67 80.26,26.78 v1(80.62,26.42) ; R23.2 94.67,39.6 94.24,39.17 v1(94.24,33.58)
  BOTTOM w0.152: v1(80.62,26.42) 80.62,26.42 83.67,29.46 83.7,29.46 84.97,30.73 90.83,30.73 93.68,33.58 v1(94.24,33.58)
LED_DAT: length 58.8
  TOP w0.152: R22.2 132.81,23.4 129.57,26.64 123.29,26.64 121.64,28.3 117.4,28.3 115.72,29.97 111.36,29.97 110.01,28.63 94.57,28.63 94.13,29.06 94.13,31.01 91.77,33.38 91.77,35.76 90.73,36.8 88.65,36.8 88.18,37.28 U1.91
LED_PWR_ON: length 74.6
  TOP w0.152: R25.2 136.93,21.89 136.4,22.43 134.65,22.43 129.92,27.15 123.45,27.15 121.9,28.7 117.6,28.7 113.95,32.36 v1(113.84,32.36) ; v1(75.32,26.37) 75.26,26.42 U1.57
  TOP w0.305: Q2.1 137.33,20.46 R25.2
  BOTTOM w0.152: v1(75.32,26.37) 76.1,25.58 80.57,25.58 85.27,30.28 91.11,30.28 93.55,32.72 94.8,32.72 95.43,33.35 112.88,33.35 113.84,32.39 v1(113.84,32.36)
MODE_1: length 7.9
  BOTTOM w0.152: RP5.2 78.83,13.83 78.34,14.33 78.34,17.07 77.74,17.67 U13.11
MODE_2: length 9.2
  BOTTOM w0.152: U13.12 78.13,18.32 78.89,17.55 78.89,14.38 79.65,13.63 RP5.3
MODE_3: length 10.4
  BOTTOM w0.152: RP5.4 80.46,13.52 79.3,14.68 79.3,18.24 78.57,18.97 U13.13
MOTOR_BRK_1: length 83.8
  TOP w0.152: R55.2 31.43,67.64 32.11,67.64 v1(32.57,68.1) 33.11,68.64 U23.28 ; v1(67.57,42.44) 67.57,43.21 64.97,45.8 v1(64.46,45.8) ; v1(81.41,38) 81.41,40.36 83.26,42.21 U1.3
  BOTTOM w0.152: v1(81.41,38) 81.23,37.82 78.49,37.82 77.6,38.71 68.99,38.71 67.57,40.13 v1(67.57,42.44) ; v1(64.46,45.8) 64.4,45.8 62.16,43.56 52.78,43.56 51.17,41.95 44.85,41.95 42.8,43.99 42.8,56.89 42.8,57.05 34.62,65.23 33.48,65.23 32.57,66.14 v1(32.57,68.1)
MOTOR_BRK_2: length 41.4
  TOP w0.152: U26.28 100.14,69.52 99.64,69.01 v1(99.64,68.66) 98.8,68.66 R67.2 ; v1(84.2,45.9) 82.76,44.45 U1.4 ; v1(99.37,56.21) 99.58,56 99.58,53.09 97.72,51.23 97.72,48.62 v1(97.49,48.39)
  BOTTOM w0.152: v1(99.64,68.66) 99.82,68.47 99.82,56.67 v1(99.37,56.21) ; v1(97.49,48.39) 95.91,48.39 93.42,45.9 v1(84.2,45.9)
MOTOR_BRK_3: length 53.4
  TOP w0.152: v1(84.65,46.9) 84.64,46.89 84.3,46.89 82.26,44.84 U1.5 ; v1(113.87,67.56) 114.01,67.42 R80.2 114.25,66.56 114.25,66.04 115.25,65.04 U29.28
  BOTTOM w0.152: v1(113.87,67.56) 113.87,65.91 113.49,65.53 113.06,65.53 109.58,62.05 109.58,52.17 107.55,50.14 95.99,50.14 93.32,47.47 85.22,47.47 v1(84.65,46.9)
MOTOR_BRK_4: length 48.3
  TOP w0.152: U1.38 68.24,35.78 v1(68.23,35.76) ; v1(34.44,48.23) 34.44,48.03 34.43,48.02 R93.2 34.38,47.41 U32.28
  BOTTOM w0.152: v1(68.23,35.76) 63.2,35.76 60.94,38.02 38.31,38.02 35.94,40.39 35.94,46.74 v1(34.44,48.23)
MOTOR_BRK_5: length 42.2
  TOP w0.152: U1.39 68.53,35.28 68.39,35.14 67.3,35.14 66.37,36.07 66.37,38.23 65.57,39.03 v1(65.44,39.03)
  TOP w0.203: U35.28 72.8,69.32 71.81,68.33 R107.2 v1(71.27,67.59)
  BOTTOM w0.152: v1(71.27,67.59) 71.27,66.98 65.76,61.47 65.76,43.87 65.44,43.55 v1(65.44,39.03)
MOTOR_DIR_1: length 87.5
  TOP w0.152: U23.26 33.32,69.67 32.79,69.67 31.87,70.6 R53.2 v1(30.7,70.6) ; v1(82.63,37.85) 82.93,38.15 82.93,38.46 84.76,40.28 U1.97 ; v1(66.98,41.45) 66.98,42.88 64.87,44.99 v1(64.56,44.99)
  BOTTOM w0.152: v1(64.56,44.99) 64.4,44.99 62.49,43.08 52.91,43.08 51.39,41.55 44.53,41.55 42.37,43.71 42.37,56.82 34.37,64.82 33.23,64.82 31.88,66.17 31.88,69.42 v1(30.7,70.6) ; v1(66.98,41.45) 66.98,39.96 68.58,38.35 77.29,38.35 78.21,37.44 82.22,37.44 v1(82.63,37.85)
MOTOR_DIR_2: length 46.7
  TOP w0.152: v1(96.85,47.6) 96.9,47.65 96.9,53.16 v1(97.03,53.29) ; U26.26 99.78,70.52 99.64,70.66 v1(99.59,70.66) 99.49,70.66 R65.2 ; v1(88.57,40.01) 88.11,40.01 87.34,40.78 U1.98
  BOTTOM w0.152: v1(96.85,47.6) 96.9,47.55 96.9,46.84 96.04,45.97 96.04,44.25 91.8,40.01 v1(88.57,40.01) ; v1(97.03,53.29) 100.71,53.29 v1(101.58,54.15) 100.74,54.99 100.74,69.77 99.85,70.66 v1(99.59,70.66) 99.34,70.66
MOTOR_DIR_3: length 53.7
  TOP w0.152: v1(116.94,67.57) 116.93,67.56 R78.2 116.93,65.7 116.25,65.02 U29.26 ; v1(85.42,46.76) 85.42,46.05 84.26,44.88 U1.1
  BOTTOM w0.152: v1(116.94,67.57) 114.45,65.07 113.13,65.07 109.98,61.93 109.98,51.92 107.37,49.3 95.91,49.3 93.47,46.86 85.52,46.86 v1(85.42,46.76)
MOTOR_DIR_4: length 71.3
  TOP w0.152: U32.26 33.38,48.84 v1(32.82,48.27) 32.78,48.23 32.01,48.23 31.46,47.69 R91.2 ; U1.2 83.76,42.05 82.04,40.34 82.04,35.9 82.04,35.76 81.31,35.03 v1(81.31,34.98)
  BOTTOM w0.152: v1(81.31,34.98) 81.23,34.98 81.1,34.85 75.64,34.85 73.79,36.7 62.99,36.7 61.19,38.51 38.56,38.51 36.4,40.67 36.4,47.09 34.65,48.84 33.39,48.84 v1(32.82,48.27)
MOTOR_DIR_5: length 46.9
  TOP w0.152: v1(63.81,38) 63.81,37.49 67.02,34.28 U1.41 ; U35.26 72.38,70.32 72.24,70.46 v1(72.19,70.46) 72.09,70.46 R104.2
  BOTTOM w0.152: v1(72.19,70.46) 70.61,68.89 70.61,67.16 65.23,61.77 65.23,43.84 63.81,42.42 v1(63.81,38)
MOTOR_PWM_1: length 66.6
  TOP w0.152: v1(61.55,44.17) 61.55,42.14 64.89,38.8 64.89,38.79 65.21,38.47 65.22,38.47 65.51,38.18 65.63,38.18 v1(65.67,38.14) 65.71,38.1 65.71,36.09 67.02,34.78 U1.40 ; R54.2 31.44,69.14 v1(32.44,69.14) U23.27
  BOTTOM w0.152: v1(32.44,69.14) 32.74,69.14 33.2,68.68 33.2,66.11 33.65,65.66 34.88,65.66 43.23,57.3 43.23,44.4 44.48,43.15 49.05,43.15 50.07,44.17 v1(61.55,44.17)
MOTOR_PWM_2: length 63.7
  TOP w0.152: v1(100.59,54.08) 100.59,52.43 99.21,51.05 99.21,48.34 v1(99.16,48.29) ; U1.42 71.5,33.78 72.14,34.42 v1(72.14,34.87) ; U26.27 99.81,70.02 v1(99.56,69.77) 98.9,69.77 R66.2
  BOTTOM w0.152: v1(100.59,54.08) 100.28,54.38 100.28,69.16 99.67,69.77 v1(99.56,69.77) ; v1(72.14,34.87) 74.61,34.87 76.29,33.2 81.21,33.2 81.66,33.66 87.15,33.66 88.52,35.03 88.52,37.52 90.17,39.17 92.31,39.17 98.25,45.11 98.25,47.32 99.16,48.23 v1(99.16,48.29)
MOTOR_PWM_3: length 70.6
  TOP w0.152: R79.2 115.75,66.52 v1(115.75,65.35) U29.27 ; U1.44 71.67,32.78 72.9,34.01 v1(72.95,34.01)
  BOTTOM w0.152: v1(72.95,34.01) 74.96,34.01 76.1,32.87 76.12,32.87 76.14,32.84 81.43,32.84 81.89,33.3 87.3,33.3 87.35,33.35 87.45,33.35 88.88,34.77 88.88,37.26 90.43,38.81 92.56,38.81 98.66,44.91 98.66,45.95 101.35,48.64 107.5,48.64 110.39,51.54 110.39,61.8 113.21,64.62 115.02,64.62 v1(115.75,65.35)
MOTOR_PWM_4: length 50.2
  TOP w0.152: U32.27 33.88,48.49 33.68,48.29 v1(33.63,48.29) 33.63,48.03 R92.2 ; U1.45 68.36,32.28 v1(68.3,32.33)
  BOTTOM w0.152: v1(33.63,48.29) 33.63,48.23 35.46,46.41 35.46,39.85 38,37.31 60.89,37.31 62.87,35.33 65.05,35.33 68.05,32.33 v1(68.3,32.33)
MPU_INT: length 10.7
  TOP w0.152: U1.8 80.73,43.43 U3.12 83.86,49.8 R4.2
MR_BALL_PWM: length 57.4
  TOP w0.152: U1.96 84.79,39.78 83.57,38.56 v1(83.57,38.28) ; R105.2 71.5,69.57 v1(72.16,69.57) 72.41,69.82 U35.27
  BOTTOM w0.152: v1(72.16,69.57) 71.99,69.4 71.99,67.03 66.12,61.16 66.12,43.61 65.89,43.38 65.89,39.4 67.26,38.02 68.41,38.02 68.43,38 77.14,38 78.06,37.08 82.88,37.08 83.57,37.77 v1(83.57,38.28)
MUTE: length 141.8
  TOP w0.152: v1(73.51,30.94) 73.51,31.85 74.27,32.61 74.27,37.06 73.05,38.28 U1.33 ; U40.1 125.66,32.36 v1(125.28,32.74) ; v1(38.28,23.72) 38.31,23.69 39.46,23.69 U38.15 42.93,23.72 44.68,21.97 53.16,21.97 53.72,22.53 69.45,22.53 70.79,23.88 v1(70.79,23.9) 70.81,23.9 71.73,24.82 v1(71.73,26.16) ; U39.1 v1(22.6,32)
  BOTTOM w0.152: v1(22.6,32) 22.6,26.3 23.37,25.53 35,25.53 36.28,24.25 R113.1 v1(38.28,23.72) 41.89,23.72 TP53.1 ; v1(125.28,32.74) 123.52,32.74 121.11,30.33 112.04,30.33 110.37,32 96.52,32 95.84,31.32 94.29,31.32 91.87,28.91 85.91,28.91 80.9,23.9 v1(70.79,23.9) ; v1(73.51,30.94) 73.51,30.53 71.73,28.75 v1(71.73,26.16)
NEXT: length 49.4
  TOP w0.152: v1(37.46,14.12) 37.76,13.82 U38.6 42.22,13.82 47.83,19.43 72.6,19.43 76.86,23.69 76.86,25.85 76.89,25.88 76.89,25.96 77.26,26.33 U1.61
  BOTTOM w0.152: v1(37.46,14.12) R111.1
NRST: length 34.5
  TOP w0.152: v1(78.77,34.29) 78.74,34.32 78.67,34.32 77.78,35.2 77.78,41.48 v1(77.88,41.58) ; R7.2 v1(98.53,34.82) ; v1(87.51,35.82) 88.62,35.82 89.29,35.15 89.99,35.15 90.27,35.43 v1(90.27,36.02)
  TOP w0.203: v1(77.88,41.58) 77.76,41.7 U1.14
  BOTTOM w0.152: v1(77.88,41.58) 77.9,41.55 ; v1(98.53,34.82) 98.53,35.28 TP1.1 v1(90.27,36.02) ; v1(78.77,34.29) 78.79,34.29 78.87,34.37 86.59,34.37 87.51,35.28 v1(87.51,35.82)
  BOTTOM w0.203: 77.12,41.55 77.14,41.58 v1(77.88,41.58)
  BOTTOM w0.254: 78.72,41.55 R11.2 77.9,41.55 ; 77.12,41.55 C18.1
NUM_1: length 12.4
  BOTTOM w0.152: U11.3 63.13,19.7 61.75,18.31 61.75,15.14 63.17,13.72 64.49,13.72 64.92,13.29 RP3.1
NUM_2: length 11.8
  BOTTOM w0.152: U11.4 63.09,19.05 62.13,18.08 62.13,15.34 63.38,14.1 64.72,14.1 65.73,13.09 RP3.2
NUM_3: length 11.2
  BOTTOM w0.152: RP3.3 66.58,11.48 66.58,12.9 64.95,14.53 63.6,14.53 62.49,15.65 62.49,17.88 63,18.39 U11.5
NUM_4: length 10.4
  BOTTOM w0.152: RP3.4 67.36,11.45 67.36,12.78 65.25,14.88 63.75,14.88 62.95,15.69 62.95,17.35 63.34,17.74 U11.6
PREV: length 48.6
  TOP w0.152: U1.60 76.76,26.36 76.51,26.11 76.51,23.95 72.44,19.89 47.47,19.89 42.51,14.92 U38.7 38.06,14.92 v1(37.36,15.62)
  BOTTOM w0.152: v1(37.36,15.62) R112.1
RF_CE: length 39.8
  TOP w0.152: J3.2 120.63,26.87 119.66,27.84 117.32,27.84 115.62,29.54 111.71,29.54 109.68,27.51 94.03,27.51 88.29,33.25 85.91,33.25 U1.83
RF_FREQ_1: length 14.1
  BOTTOM w0.152: RP1.1 51.62,11.65 51.62,13.46 53.52,15.37 59.34,15.37 60.12,16.15 60.12,17.42 59.8,17.74 U11.11
RF_FREQ_2: length 14.5
  BOTTOM w0.152: U11.12 59.92,18.39 60.48,17.83 60.48,16.01 60.45,15.98 60.45,15.9 59.54,14.99 54.28,14.99 52.38,13.08 52.38,11.7 RP1.2
RF_FREQ_3: length 14.8
  BOTTOM w0.152: RP1.3 53.29,11.69 53.29,12.98 54.92,14.61 59.82,14.61 60.84,15.62 60.84,18.06 59.85,19.05 U11.13
RF_FREQ_4: length 15
  BOTTOM w0.152: RP1.4 54.04,11.67 54.04,12.43 55.78,14.17 59.89,14.17 61.19,15.47 61.19,18.34 59.83,19.7 U11.14
RF_IRQ: length 37
  TOP w0.152: v1(109.45,26.47) 103.53,26.47 103.3,26.7 93.35,26.7 87.79,32.25 85.91,32.25 U1.81 ; J3.7 114.15,26.04 114.15,24.05 112.68,22.58 R12.1 110.29,22.66 v1(110.29,23.85)
  BOTTOM w0.152: v1(110.29,23.85) 110.29,25.53 109.45,26.37 v1(109.45,26.47)
RF_SPI_NCS: length 38.2
  TOP w0.152: J3.3 119.36,26.72 118.67,27.41 117.15,27.41 115.47,29.08 111.99,29.08 109.93,27.03 103.48,27.03 103.45,27.05 93.7,27.05 87.97,32.78 U1.82
RS232_1_RX: length 48
  TOP w0.152: v1(29.92,27.86) 42.88,27.86 46.53,31.52 46.53,32.36 47.32,33.15 48.22,33.15 U4.13
  TOP w0.305: v1(25.12,26.89) 24.48,27.53 7.06,27.53 5.43,25.9 5.43,24.91
  BOTTOM w0.152: v1(29.92,27.86) 28.75,26.7 25.28,26.7 25.12,26.85 v1(25.12,26.89)
RS232_1_TX: length 45
  TOP w0.152: U4.14 46.98,33.77 45.93,32.72 45.93,31.72 42.62,28.42 v1(31.4,28.42)
  TOP w0.305: J2.2 8.52,23.94 10.91,26.34 v1(23.73,26.34)
  BOTTOM w0.152: v1(31.4,28.42) 31.32,28.35 29.14,26.16 23.9,26.16 v1(23.73,26.34)
RS232_2_RX: length 17.4
  TOP w0.152: U4.8 41.77,30.52 41,29.74 35.79,29.74 28.96,36.58 28.35,36.58 J6.5
RS232_2_TX: length 15.6
  TOP w0.152: J6.6 30.81,35.36 35.99,30.18 40.69,30.18 41.68,31.17 U4.7
RSTN: length 67
  TOP w0.152: v1(71.76,23.14) 71.94,23.14 72.65,23.85 v1(72.65,25.86) ; v1(71.5,20.83) 71.38,20.96 62.26,20.96 61.65,20.35 59.95,20.35 59.34,20.96 55.25,20.96 55.25,20.93 54.74,20.42 47.32,20.42 47.26,20.49 42.8,16.02 U38.8 38.19,16.02 v1(37.09,17.12) ; v1(74.37,30.43) 74.91,30.96 74.91,35.64 76.74,37.47 76.74,41.05 75.76,42.03 U1.18
  BOTTOM w0.152: Q19.3 36.28,19.92 R119.1 36.38,17.12 v1(37.09,17.12) ; v1(71.76,23.14) 71.5,22.89 v1(71.5,20.83) ; v1(72.65,25.86) 72.44,26.06 72.44,28.91 73.97,30.43 v1(74.37,30.43)
SHOOT: length 46.2
  TOP w0.152: v1(97.55,51.86) 97.65,51.86 98.08,52.28 U18.2 98.08,58.23 98.86,59 98.86,59.48 R29.1 ; U1.25 72.26,44.66 71.17,45.75 69.06,45.75 v1(68.43,46.38)
  BOTTOM w0.152: v1(68.43,46.38) 68.28,46.53 68.28,47.27 69.27,48.26 91.24,48.26 94.83,51.86 v1(97.55,51.86)
SHOOT_2: length 28.4
  TOP w0.152: v1(104.52,46.05) 103.46,47.12 99.24,47.12 98.43,47.93 98.43,51.31 99.98,52.86 99.98,57.12 100.46,57.61 U19.2 101.23,57.72 U18.4 ; v1(105.18,42.42) 105.16,42.39 105.16,41.07 106.07,40.16 R26.2
  BOTTOM w0.152: v1(104.52,46.05) 104.52,45.75 105.18,45.09 v1(105.18,42.42)
SHOOT_OFF: length 40.9
  TOP w0.152: U20.4 54.28,45.06 54.61,44.73 54.61,41.33 R38.1 55.48,41.68 R34.2 56.19,41.43 57.51,40.11 62.59,40.11 v1(64.76,37.93) ; U1.7 81.26,42.47 80.9,42.11 80.9,38.25 80.65,38 80.65,36.47 80.34,36.17 v1(80.27,36.17)
  BOTTOM w0.152: v1(80.27,36.17) 75.72,36.17 74.42,37.47 65.23,37.47 v1(64.76,37.93)
SHOOT_OUT: length 76
  TOP w0.152: 117.71,45.56 117.71,51 v1(117.35,51.36) ; 117.71,45.56 117.71,43.36 116.11,41.76 U16.4 ; 117.71,45.56 113.65,45.56 113.29,45.92 113.29,47.96 109.45,51.79 v1(106.91,51.79) ; U19.7 v1(108.18,57.61)
  BOTTOM w0.152: J9.3 128.72,84.96 TP13.1 127.64,83.88 127.64,79.38 125.81,77.55 121.36,77.55 119.56,75.74 119.56,62.36 117.43,60.22 117.43,51.44 v1(117.35,51.36) ; v1(106.91,51.79) 108.49,53.37 108.49,57.35 108.23,57.61 v1(108.18,57.61)
SPI_MISO: length 35.1
  TOP w0.152: J3.6 115.55,27.68 114.96,28.27 112.85,28.27 109.91,25.32 103.15,25.32 102.52,25.96 92.79,25.96 87.47,31.28 U1.79
SPI_MOSI: length 36.3
  TOP w0.152: U1.80 87.68,31.78 93.12,26.34 102.72,26.34 103.3,25.76 109.6,25.76 112.52,28.68 115.29,28.68 116.82,27.15 J3.5
SPI_SCK: length 40.2
  TOP w0.152: U1.78 87.41,30.78 92.59,25.6 102.19,25.6 102.87,24.92 110.06,24.92 112.8,27.66 v1(114,27.66) ; J3.4 117.96,26.04 117.96,24.89 117.22,24.16 v1(114.94,24.16)
  BOTTOM w0.152: v1(114,27.66) 114,25.1 v1(114.94,24.16)
SPK_L_N: length 12.6
  TOP w0.152: U38.24 26.78,17.12 27.18,17.53 C102.1
SPK_L_P: length 14.5
  TOP w0.152: C103.1 28.73,28.09 27.69,27.05 27.69,16.59 27.08,15.98 26.04,15.98 U38.25
SPK_R_N: length 109.6
  TOP w0.152: v1(44.38,25.88) 44.38,26.11 43.79,26.7 30.56,26.7 28.96,25.1 28.96,14.91 27.87,13.82 U38.27 ; C107.1 v1(118.11,32.74)
  BOTTOM w0.152: v1(118.11,32.74) 116.94,31.57 112.63,31.57 111.2,32.99 95.89,32.99 95.13,32.23 93.8,32.23 91.47,29.9 85.65,29.9 80.65,24.89 45.37,24.89 v1(44.38,25.88)
SPK_R_P: length 110.1
  TOP w0.152: v1(43.51,27.25) 30.25,27.25 28.35,25.35 28.35,15.32 27.96,14.92 U38.26 ; C108.1 v1(118.26,31.06)
  BOTTOM w0.152: v1(43.51,27.25) 43.51,25.43 44.43,24.51 80.85,24.51 85.75,29.41 91.65,29.41 94.03,31.8 95.53,31.8 96.27,32.54 110.75,32.54 112.22,31.06 v1(118.26,31.06) 118.3,31.1
UART1_RX: length 38.8
  TOP w0.152: U1.69 81.26,31.37 v1(81.24,31.38) ; v1(50.09,33.4) 49.16,32.47 U4.12
  BOTTOM w0.152: v1(50.09,33.4) 50.42,33.4 52.76,31.06 70.06,31.06 71.55,32.56 71.56,32.56 71.71,32.72 74.65,32.72 75.62,31.75 80.87,31.75 v1(81.24,31.38)
UART1_TX: length 37.5
  TOP w0.152: v1(50.29,32.59) 49.52,31.82 U4.11 ; v1(80.44,30.96) 80.44,30.94 80.76,30.62 U1.68
  BOTTOM w0.152: v1(50.29,32.59) 50.55,32.59 52.45,30.68 70.18,30.68 71.86,32.36 74.4,32.36 75.36,31.39 80.01,31.39 v1(80.44,30.96)
UART2_RX: length 50.3
  TOP w0.152: v1(89.94,33.32) 89.94,33.96 88.64,35.27 85.89,35.27 U1.87 ; U4.9 50.09,30.52 50.5,30.92 v1(50.5,30.96)
  BOTTOM w0.152: v1(50.5,30.96) 50.68,30.96 51.74,29.9 70.49,29.9 72.19,31.6 74.14,31.6 75.06,30.68 79.22,30.68 79.86,30.05 82.48,30.05 84.48,32.05 87.38,32.05 88.21,32.88 89.5,32.88 v1(89.94,33.32)
UART2_TX: length 48.7
  TOP w0.152: U4.10 49.69,31.17 v1(50.29,31.78) ; v1(89.26,33.76) 89.26,34.09 88.56,34.78 U1.86
  BOTTOM w0.152: v1(50.29,31.78) 50.6,31.78 52.12,30.25 70.28,30.25 71.99,31.95 74.3,31.95 75.21,31.04 79.55,31.04 80.19,30.4 82.33,30.4 84.34,32.41 84.43,32.41 84.61,32.59 87.3,32.59 87.99,33.27 88.94,33.27 89.26,33.59 v1(89.26,33.76)
USB_DM: length 13.6
  TOP w0.152: R16.1 88.55,21.13 88.04,21.64 82.91,21.64 81.84,22.71 81.84,27.25 81.76,27.34 U1.70
USB_DP: length 13
  TOP w0.152: U1.71 82.26,27.31 82.2,27.25 82.2,22.89 83.09,22 87.99,22 88.62,22.63 R17.1
USB_V_EN: length 28.6
  TOP w0.152: R14.2 103.25,20.8 U5.4 v1(102.24,20.85) ; v1(102.21,28.07) 94.11,28.07 88.4,33.78 U1.84
  BOTTOM w0.152: v1(102.21,28.07) 102.03,27.89 102.03,21.06 v1(102.24,20.85)
USB_VBUS: length 8.8
  TOP w0.152: C33.1 99.58,21.76 99.58,22.13 99.6,22.15 99.6,22.33 100,22.73 U5.1 ; C32.1 96.4,21.84 U7.5
  TOP w0.254: U6.1 98.83,20.18 C33.1 98.66,21.18 C32.1
VOL+: length 65.7
  TOP w0.152: U1.46 70.64,31.78 72.01,31.78 72.7,31.09 v1(72.7,30.99) ; 39.69,11.62 U38.4 37.86,11.62 v1(37.36,11.12) 37.21,11.12 35.31,13.03 35.31,25.2 v1(36.12,26.01) 41.99,26.01 45.54,22.45 52.55,22.45 53.14,23.04 68,23.04 71.02,26.06 v1(71.02,28.78)
  BOTTOM w0.152: v1(37.36,11.12) R109.1 ; v1(71.02,28.78) 71.02,29.31 v1(72.7,30.99)
VOL-: length 50.3
  TOP w0.152: v1(37.5,12.69) 37.53,12.72 U38.5 41.99,12.72 48.26,19 72.67,19 77.22,23.55 77.22,25.7 77.76,26.24 U1.62
  BOTTOM w0.152: v1(37.5,12.69) 36.35,12.69 R110.1
N16212342: length 5.5
  TOP w0.254: U1.21 74.26,44.45 v1(74.04,44.67)
  BOTTOM w0.254: v1(74.04,44.67) 74.04,44.75 C10.1 C9.1 R10.1
N16212746: length 12
  TOP w0.152: 92.46,20.9 92.23,21.13 R16.2 90.93,18.95 92.41,17.48 96.5,17.48 97.34,18.32 U6.2
N16212776: length 7.2
  TOP w0.152: R17.2 91.09,22.78 93.32,22.78 93.75,22.35 93.75,20.32 94.9,19.17 U6.3
N16213098: length 2.5
  TOP w0.152: U3.10 79.73,51.06 v1(79.33,51.46)
  BOTTOM w0.152: C7.1 79.33,50.85 v1(79.33,51.46)
N16213170: length 1.9
  TOP w0.152: U3.20 80.23,54.24 C8.1
N16214174: length 4.3
  TOP w0.152: J1.4 99.51,34.78 R7.1
N16214228: length 5
  TOP w0.152: R15.2 103.86,21.79 102.34,21.79 101.4,20.85 U5.3
N16214444: length 2.8
  TOP w0.254: Q1.1 81.23,58.19 R9.2 80.01,58.01
N16214506: length 7.9
  TOP w0.254: Q1.3 89.64,61.65 LS1.2
N16216300: length 6.3
  TOP w0.152: U1.13 78.26,45.43 v1(78.43,45.6)
  BOTTOM w0.152: v1(78.43,45.6) 78.19,45.36 77.51,45.36 Y1.1 75.36,46.04 C2.2
N16216320: length 6.4
  TOP w0.152: U1.12 78.76,44.94 v1(79.18,45.36)
  BOTTOM w0.152: v1(79.18,45.36) 80.43,45.36 Y1.2 82.3,46.04 C1.2
N16216718: length 3.7
  TOP w0.152: U1.49 68.51,30.28 67.97,29.74 C23.1
N16216722: length 5.1
  TOP w0.203: C22.1 83.82,26.29 83.26,26.85 U1.73
N16216872: length 20.3
  TOP w0.305: H1.4 H1.1 ; H1.1 H1.7 ; H1.1 H1.6 ; H1.1 H1.8 ; H1.1 H1.9 ; H1.1 H1.3 ; H1.1 H1.5 ; H1.1 H1.2
N16216974: length 20.3
  TOP w0.305: H2.1 H2.7 ; H2.1 H2.4 ; H2.1 H2.3 ; H2.1 H2.9 ; H2.1 H2.6 ; H2.1 H2.8 ; H2.1 H2.5
  TOP w0.5: H2.1 H2.2
N16217080: length 20.3
  TOP w0.305: H3.1 H3.7 ; H3.1 H3.4 ; H3.1 H3.3 ; H3.1 H3.9 ; H3.1 H3.6 ; H3.1 H3.8 ; H3.1 H3.5 ; H3.1 H3.2
N16217240: length 20.3
  TOP w0.305: H4.7 H4.1 ; H4.1 H4.5 ; H4.1 H4.9 ; H4.1 H4.3 ; H4.1 H4.6 ; H4.1 H4.2 ; H4.1 H4.4 ; H4.1 H4.8
